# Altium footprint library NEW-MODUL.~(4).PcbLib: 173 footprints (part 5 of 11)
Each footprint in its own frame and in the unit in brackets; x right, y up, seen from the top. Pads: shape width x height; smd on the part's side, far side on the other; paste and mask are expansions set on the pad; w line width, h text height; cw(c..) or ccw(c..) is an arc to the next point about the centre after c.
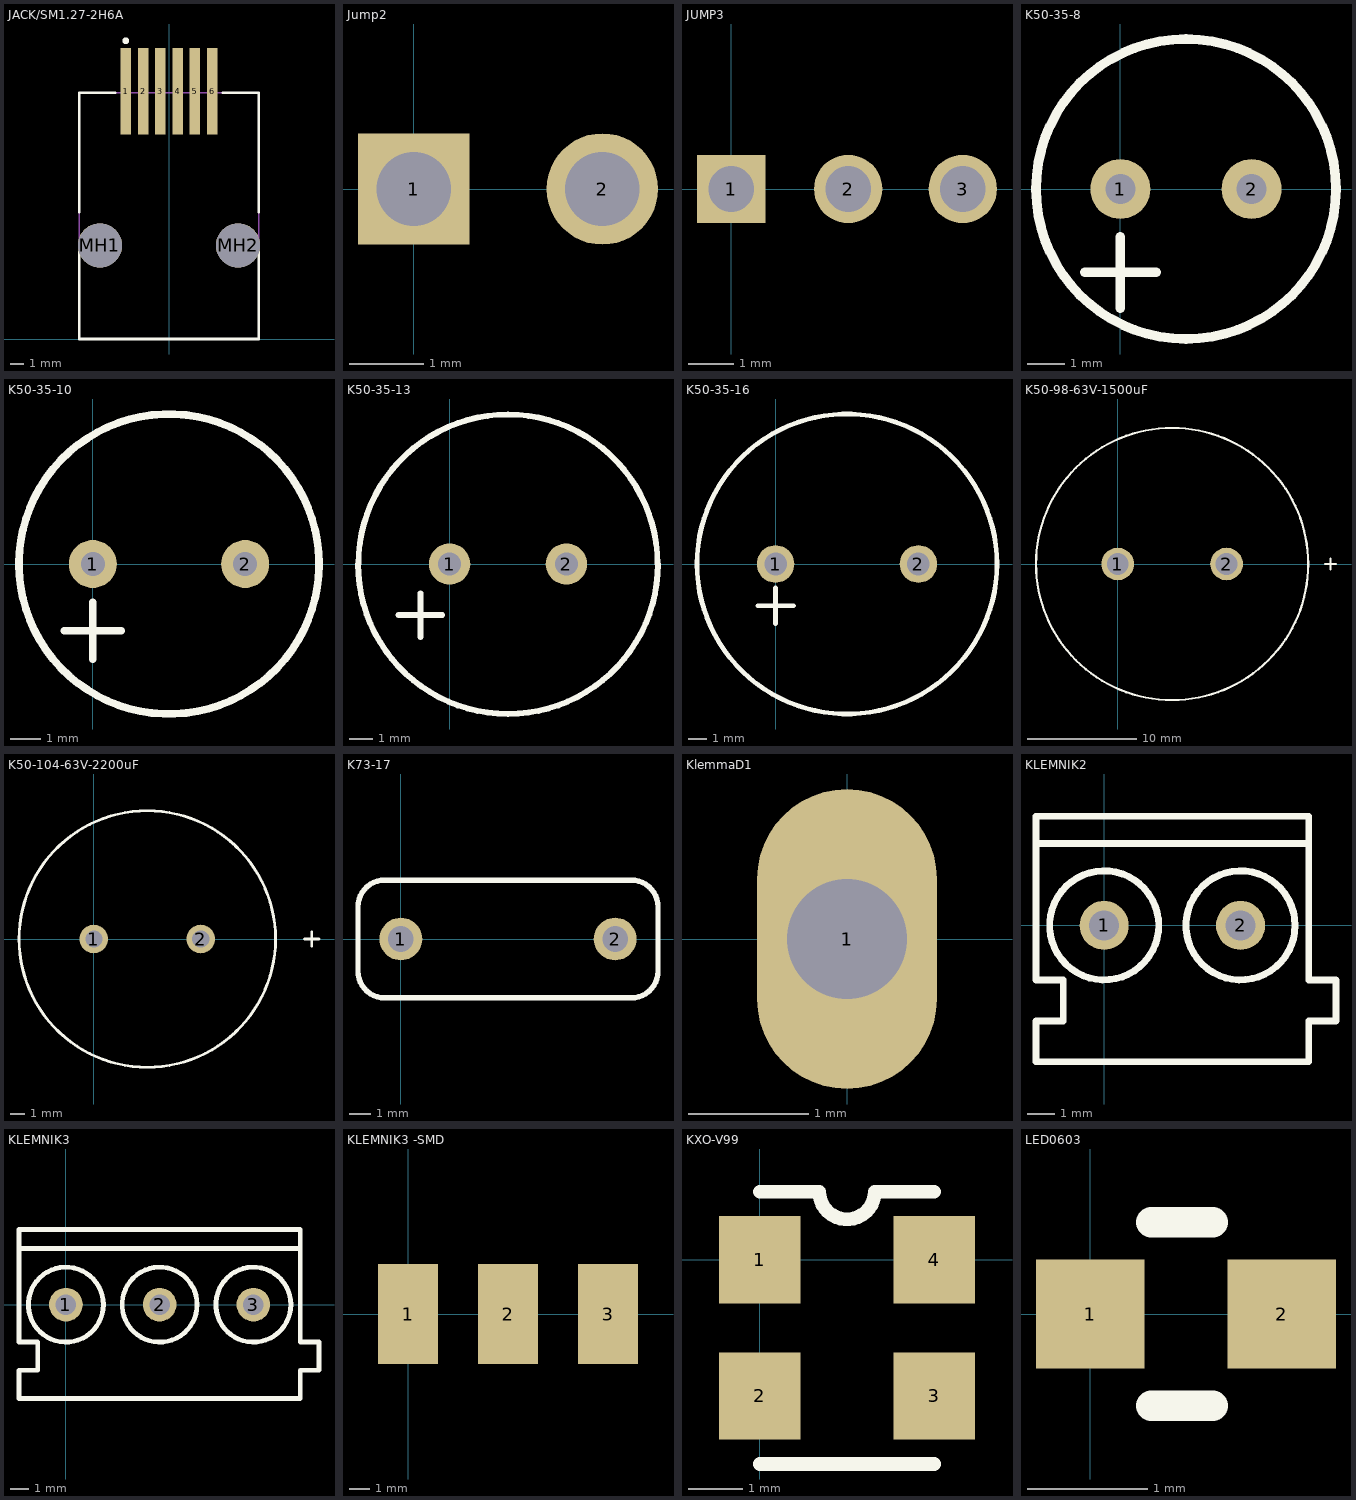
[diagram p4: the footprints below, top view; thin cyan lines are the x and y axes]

## JACK/SM1.27-2H6A [mm] "Connector; PCB Jack, SM; 1-Port, 6 Positions, 6 Loaded; Unshielded without Lightpipes; Right Angle"
height 11.75
pads (8):
  rect 0.76x6.35 smd: 1(-3.175,18.205) 2(-1.905,18.205) 3(-0.635,18.205) 4(0.635,18.205) 5(1.905,18.205) 6(3.175,18.205)
  round 3.25 hole 3.25 unplated: MH1(-5.08,6.88) MH2(5.08,6.88)
Top Overlay:
  circle w0.25: c-3.175,21.93 r0.125
  lines w0.2: -6.605,6.422 -6.605,0 6.605,0 6.605,6.422 ; -6.605,9.338 -6.605,18.1 -3.955,18.1 ; 3.955,18.1 6.605,18.1 6.605,9.338
Mechanical 13:
  lines w0.1: -6.605,0 -6.605,18.1 6.605,18.1 6.605,0 -6.605,0
3D body "Mod-Jack-K122449008-Stig-W.step": height 11.5, standoff -2.43, extent -6.709,0 6.709,20.79

## Jump2 [mm]
pads (2):
  rect 1.5x1.5 hole 1: 1(0,0)
  round 1.5 hole 1: 2(2.54,0)
3D body "User Library-PLS-1.STEP": height 8.44, standoff -3, extent -1.27,-1.27 1.27,1.27
3D body "User Library-PLS-1.STEP": height 8.44, standoff -3, extent 1.27,-1.27 3.81,1.27

## JUMP3 [mm]
pads (3):
  rect 1.5x1.5 hole 1: 1(0,0)
  round 1.5 hole 1: 2(2.565,0) 3(5.08,0)
3D body "User Library-PLS-1.STEP": height 8.44, standoff -3, extent 3.81,-1.27 6.35,1.27
3D body "User Library-PLS-1.STEP": height 8.44, standoff -3, extent 1.27,-1.27 3.81,1.27
3D body "User Library-PLS-1.STEP": height 8.44, standoff -3, extent -1.27,-1.27 1.27,1.27

## K50-35-8 [mm]
pads (2):
  round 1.6 hole 0.8 unplated: 1(0,0) 2(3.5,0)
Top Overlay:
  circle w0.254: c1.75,0 r4
  lines w0.254: -0.953,-2.222 0.953,-2.222 ; 0,-3.175 0,-1.27
3D body "User Library-Cap electro 8x11_5x3_5mm.step": height 11.79, standoff -3.71, extent -2.247,-4.025 5.803,4.025

## K50-35-10 [mm]
pads (2):
  round 1.6 hole 0.8 unplated: 1(0,0) 2(5.08,0)
Top Overlay:
  lines w0.254: -0.953,-2.222 0.953,-2.222 ; 0,-3.175 0,-1.27 ; -2.46,0 ccw(c2.54,0) 7.54,0 ccw(c2.54,0) -2.46,0
3D body "User Library-Cap electro 10x12_5x5_0mm.step": height 12.79, standoff -3.71, extent -2.485,-5.025 7.565,5.025

## K50-35-13 [mm]
pads (2):
  round 1.8 hole 1: 1(0,0) 2(5.08,0)
Top Overlay:
  lines w0.254: -3.979,0 ccw(c2.54,0) 9.059,0 ; -3.96,0 cw(c2.54,0) 9.04,0 ; -2.222,-2.222 -0.318,-2.222 ; -1.27,-3.175 -1.27,-1.27
3D body "User Library-CAPPR500-1250x2000.step": height 20, standoff -7.5, extent -3.69,-6.25 8.786,6.25

## K50-35-16 [mm]
pads (2):
  round 2 hole 1.2: 1(0,0) 2(7.62,0)
Top Overlay:
  lines w0.254: -0.953,-2.222 0.953,-2.222 ; 0,-3.175 0,-1.27 ; -4.19,0 cw(c3.81,0) 11.81,0 cw(c3.81,0) -4.19,0
3D body "User Library-00000842 - Aluminum Electrolytic capacitor 16D7M5.step": height 20, standoff -2.5, extent -4.19,-8 11.81,8

## K50-98-63V-1500uF [mm]
pads (2):
  round 3 hole 2: 1(0,0) 2(10,0)
Top Overlay:
  circle w0.2: c5,0 r12.5
  lines w0.2: 19.032,0 20.048,0 ; 19.54,-0.508 19.54,0.508

## K50-104-63V-2200uF [mm]
height 33.5
pads (2):
  round 2 hole 1.2: 1(0,0) 2(7.5,0)
Top Overlay:
  circle w0.2: c3.75,0 r9
  lines w0.2: 14.782,0 15.798,0 ; 15.29,-0.508 15.29,0.508

## K73-17 [mm]
pads (2):
  round 2 hole 1.2: 1(0,0) 2(10,0)
Top Overlay:
  lines w0.254: -2,-1.5 ccw(c-0.75,-1.5) -0.75,-2.75 10.75,-2.75 ccw(c10.75,-1.5) 12,-1.5 12,1.5 ccw(c10.75,1.5) 10.75,2.75 -0.75,2.75 ccw(c-0.75,1.5) -2,1.5 -2,-1.5
3D body "User Library-Cap 10n - 630V Poly_2009.step": height 10.92, standoff -3, extent -1.375,-2.251 11.375,2.5

## KlemmaD1 [mm]
pads (1):
  oval 1.5x2.5 hole 1: 1(0,0)
3D body "User Library-PLS-1.step": height 8.44, standoff -3, extent -1.29,-1.29 1.25,1.25

## KLEMNIK2 [mm]
pads (2):
  round 1.8 hole 1.1: 1(0,0) 2(5,0)
Top Overlay:
  circle w0.254: c0,0 r2
  circle w0.254: c5,0 r2
  lines w0.254: -2.5,3 7.5,3 ; -2.5,-5 7.5,-5 7.5,-3.5 8.5,-3.5 8.5,-2 7.5,-2 7.5,4 -2.5,4 -2.5,-2 -1.5,-2 -1.5,-3.5 -2.5,-3.5 -2.5,-5
3D body "terminal_blocks_a-tb500-to02.stp": height 9.99, standoff -3.8, extent -2.498,-4.049 8.1,4.249

## KLEMNIK3 [mm]
pads (3):
  round 1.8 hole 1.1: 1(0,0) 2(5,0) 3(10,0)
Top Overlay:
  circle w0.254: c10,0 r2
  circle w0.254: c0,0 r2
  circle w0.254: c5,0 r2
  lines w0.254: -2.5,3 12.5,3 ; -2.5,-5 -2.5,-3.5 -1.5,-3.5 -1.5,-2 -2.5,-2 -2.5,4 12.5,4 12.5,-2 13.5,-2 13.5,-3.5 12.5,-3.5 12.5,-5 -2.5,-5

## KLEMNIK3 -SMD [mm]
pads (3):
  rect 3x5 smd: 1(0,0) 2(5,0) 3(10,0)
3D body "User Library-Terminal block 3 POS.STEP": height 3.59, standoff -3.91, extent -2.62,-0.548 12.62,12.5

## KXO-V99 [mm]
pads (4):
  rect 1.5x1.6 smd: 1(0,0) 2(0,-2.5) 3(3.2,-2.5) 4(3.2,0)
Top Overlay:
  lines w0.254: 0,-3.75 3.2,-3.75 ; 0,1.25 1.092,1.25 ccw(c1.6,1.25) 2.108,1.25 3.2,1.25
3D body "User Library-Crystal.step": height 0.9, standoff -0.05, extent -0.025,-3.77 3.175,1.23

## LED0603 [mm]
pads (2):
  rect 0.9x0.9 smd: 1(0,0) 2(1.587,0)
Top Overlay:
  lines w0.254: 0.508,-0.762 1.016,-0.762 ; 0.508,0.762 1.016,0.762
3D body "User Library-LED SMD0603.step": height 0.68, standoff 0, extent -0.038,-0.344 1.612,0.381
